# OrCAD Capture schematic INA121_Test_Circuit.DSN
size A; title: INA121 FET-Input, Low Power Instrumentation Amplifier; rev: 1.1; note: Datasheet: SBOS078  EVM : N/A
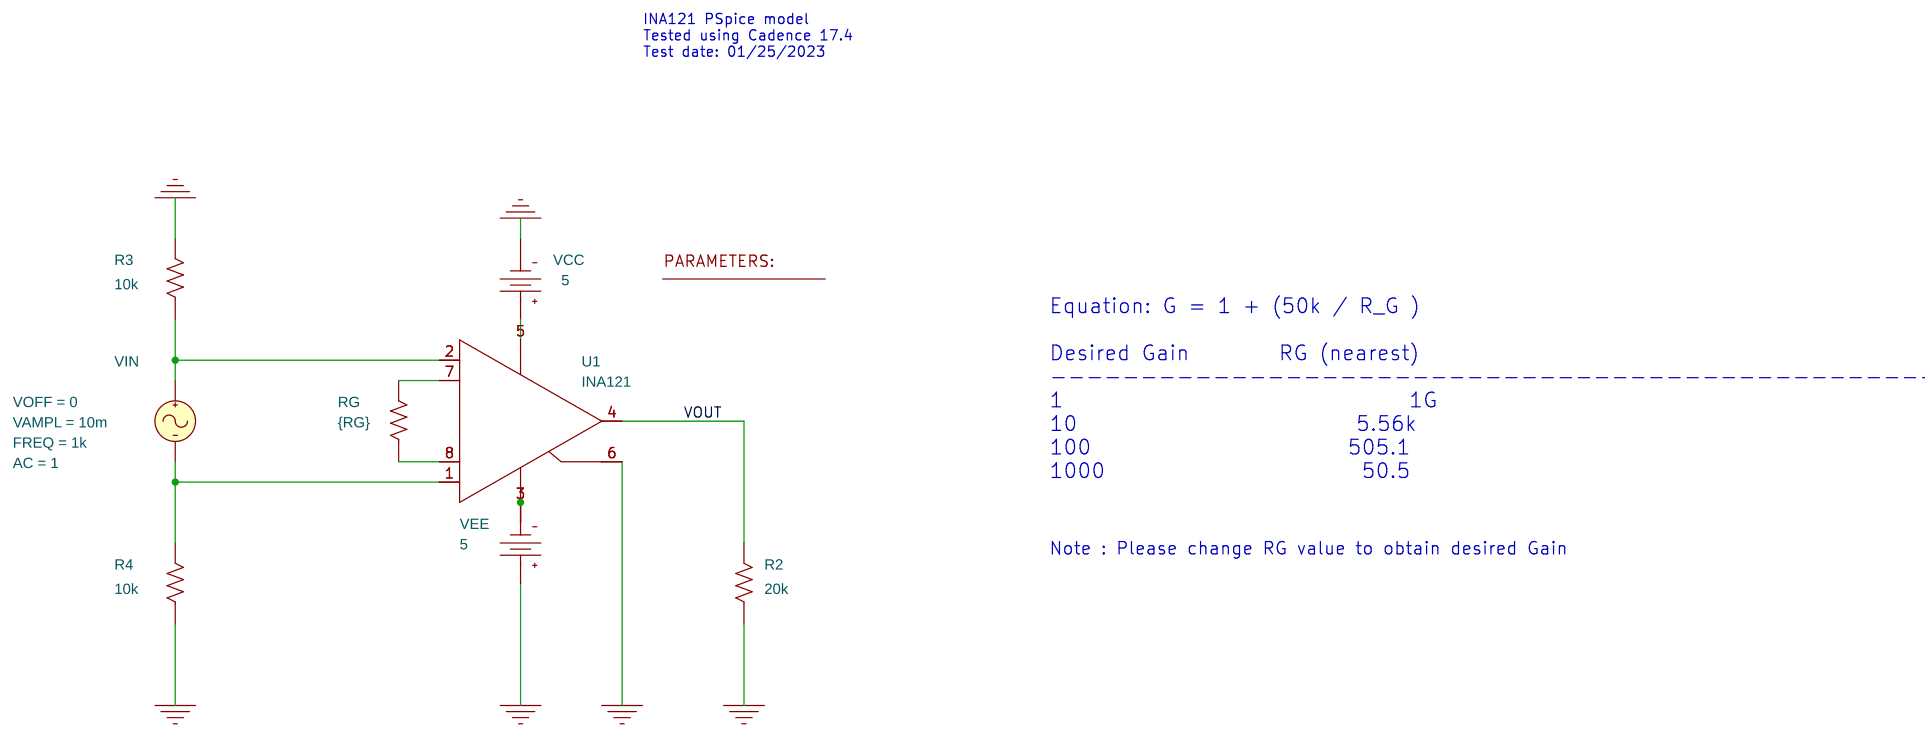
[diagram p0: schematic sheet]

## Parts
1  PARAM
R2  20k  [AX/RC05]
R3  10k  [AX/RC05]
R4  10k  [AX/RC05]
RG  {RG}  [AX/RC05]
U1  INA121
VCC  VDC
VEE  VDC
VIN  VSIN

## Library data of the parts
1 = PARAM: RG: 505.1
R2-R4 RG = R
U1 = INA121
VCC VEE = VDC: DC: 5
VIN = VSIN: AC: 1; FREQ: 1k; VAMPL: 10m; VOFF: 0

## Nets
0: R2.1 R3.2 R4.1 U1.6(REF) VCC.1(-) VEE.0(+)
VOUT: R2.2 U1.4(OUT)
N14300126: RG.2 U1.7(RG+)
N14300130: RG.1 U1.8(RG-)
N14300245: R4.2 U1.1(+) VIN.2(-)
N14300266: R3.1 U1.2(-) VIN.1(+)
N14300680: U1.5(V+) VCC.0(+)
N14300699: U1.3(V-) VEE.1(-)

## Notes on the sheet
- INA121 PSpice model
  Tested using Cadence 17.4
  Test date: 01/25/2023
- Equation: G = 1 + (50k / R_G )
  Desired Gain        RG (nearest)
  ----------------------------------------------------
  1                               1G
  10                         5.56k
  100                       505.1
  1000                       50.5
- Note : Please change RG value to obtain desired Gain
